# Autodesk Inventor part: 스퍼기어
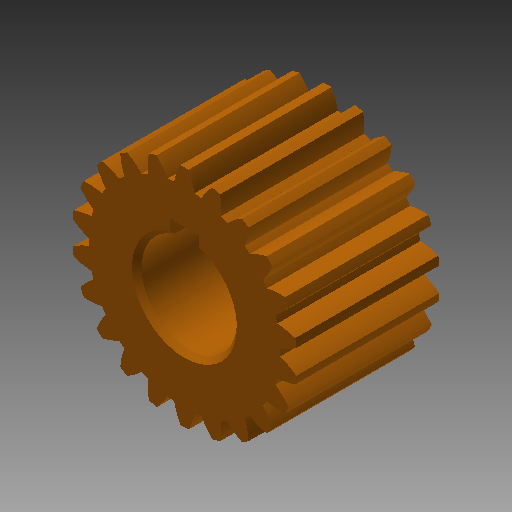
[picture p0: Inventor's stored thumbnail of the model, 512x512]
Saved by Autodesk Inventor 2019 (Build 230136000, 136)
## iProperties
Created: 2019-03
Part Number: 스퍼기어
Material: 강철
Document SubType Name: Modeling
Designer: mduedu
Categories: <?xml version="1.0" encoding="UTF-16"?> <MemberInstance><Categories><FamilyTemplate><FamilyTemplateParameter ValueType="xs:double" Id="1" ObjectReferenceKey="da
Density: 1 g/cm^3
Appearance: 주황색
CustomPartVersion: 1
Author: mduedu
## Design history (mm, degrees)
sketch "Sketch1"
  geometry: C1 r 23.6 at (0, 0)
  constraints: 1 centre point
  dimensions: "d0" = 47.2 diameter of C1 (= da_da)
extrude "Extrusion1" new body sketch "Sketch1" distance "d1" = 30 (= da_b); taper "d2" = 0 deg
workplane "Work Plane2"
sketch "Sketch2"
  geometry: C1 r 23.6 at (0, 0) reference; C2 r 22 at (0, 0)
  constraints: 1 centre point, 1 coincident
  dimensions: "d3" = 44 diameter of C2 (= da_dw)
feature "피치 지름" sketch "Sketch2" dims "d4" = 10, "d5" = 0
workplane "Work Plane8"
workplane "Work Plane9"
feature "스퍼 기어" dims "da_b" = 30, "da_d" = 44, "da_aw" = 44, "da_da" = 47.2, "da_df" = 40.172, "da_dw" = 44, angle "da_beta" = 0 deg, "da_lefttooth" = 0, "da_righttooth" = 0
sketch "스케치3"
  geometry: L1 (-3, 9.539)-(3, 9.539); L2 (3, 9.539)-(3, 12.8); L3 (3, 12.8)-(-3, 12.8); L4 (-3, 12.8)-(-3, 9.539); A1 r 10 centre (0, 0) between (-3, 9.539) and (3, 9.539); 1 further point
  constraints: 8 end point, 2 parallel, 2 point on circle, 1 centre point, 1 coincident, 1 horizontal, 1 perpendicular
  dimensions: "d49" = 20 diameter of A1; "d50" = 6 distance of L2.end L3.end; "d51" = 22.8 dimension on A1 L3
extrude "돌출2" cut sketch "스케치3" extent not by distance; stored distance "d52" = 10; taper "d53" = 0 deg
chamfer "모따기1" distance "d54" = 1; stored, may be unused: second distance "d55" = 2, angle "d56" = 45 deg
body "Solid1"
body "Srf1"
other parameters: "d16" = 44 (= da_aw), "d17" = 0, "d34" = 1.428 (computed from da_z), "d39" = 0, "d41" = 0, "d43" = 44 (= da_aw), "d46" = 44 (= da_aw), "d47" = 0, "d48" = 0
